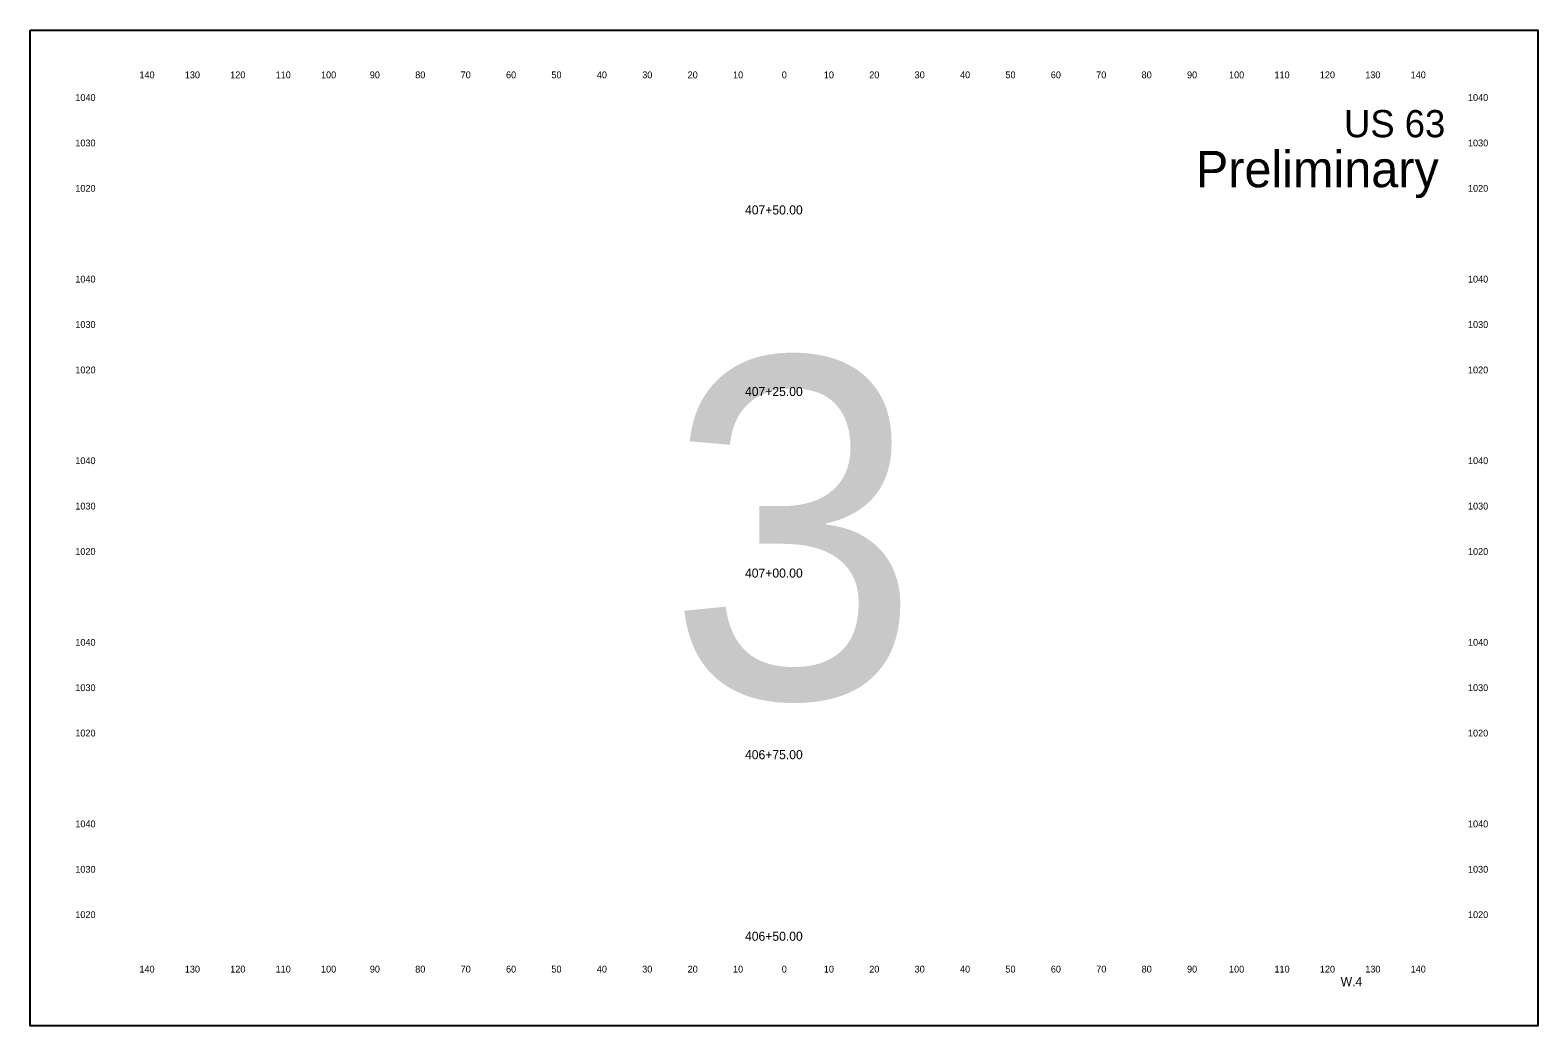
# Model space of a CAD drawing. Extents: x 10123 to 17295, y 9730 to 10181.
# Drawn here: x 10843.2 to 11175.3, y 9730.3 to 9949.6 of the extents above; entities that cross this region are included whole.
import ezdxf

# ---------------------------------------------------------------- set-up
doc = ezdxf.new("R2010")
doc.units = 0
for name, color, linetype in [('dsnTextCpn', 7, 'Continuous'), ('dsnTextCpnTitleSheetLocDesc', 7, 'Continuous'), ('dsnTextCpnTitleSheetPIN', 7, 'Continuous'), ('dsnTextCpnTitleSheetWorkType', 7, 'Continuous')]:
    doc.layers.add(name, color=color, linetype=linetype)

msp = doc.modelspace()

# ---------------------------------------------------------------- linework, layer by layer
at = {"layer": 'dsnTextCpnTitleSheetWorkType'}
msp.add_lwpolyline([(10843.21, 9949.6), (11175.29, 9949.6), (11175.29, 9730.26), (10843.21, 9730.26)], close=True, dxfattribs=at)

# ---------------------------------------------------------------- texts
at = {"layer": 'dsnTextCpn'}
for s, height, p in [('140', 1.5, (10867.27, 9939)), ('130', 1.5, (10877.27, 9939)), ('120', 1.5, (10887.27, 9939)), ('110', 1.5, (10897.27, 9939)), ('100', 1.5, (10907.27, 9939)), ('90', 1.5, (10918.02, 9939)), ('80', 1.5, (10928.02, 9939)), ('70', 1.5, (10938.02, 9939)), ('60', 1.5, (10948.02, 9939)), ('50', 1.5, (10958.02, 9939)), ('40', 1.5, (10968.02, 9939)), ('30', 1.5, (10978.02, 9939)), ('20', 1.5, (10988.02, 9939)), ('10', 1.5, (10998.02, 9939)), ('0', 1.5, (11008.76, 9939)), ('0', 1.5, (11008.76, 9939)), ('10', 1.5, (11018.02, 9939)), ('20', 1.5, (11028.02, 9939)), ('30', 1.5, (11038.02, 9939)), ('40', 1.5, (11048.02, 9939)), ('50', 1.5, (11058.02, 9939)), ('60', 1.5, (11068.02, 9939)), ('70', 1.5, (11078.02, 9939)), ('80', 1.5, (11088.02, 9939)), ('90', 1.5, (11098.02, 9939)), ('100', 1.5, (11107.27, 9939)), ('110', 1.5, (11117.27, 9939)), ('120', 1.5, (11127.27, 9939)), ('130', 1.5, (11137.27, 9939)), ('140', 1.5, (11147.27, 9939)), ('1040', 1.5, (10853.15, 9934)), ('1040', 1.5, (11159.9, 9934)), ('US 63', 6, (11132.6, 9926)), ('1030', 1.5, (10853.15, 9924)), ('1030', 1.5, (11159.9, 9924)), ('1020', 1.5, (10853.15, 9914)), ('1020', 1.5, (11159.9, 9914)), ('407+50.00', 2, (11000.66, 9909)), ('1040', 1.5, (10853.15, 9894)), ('1040', 1.5, (11159.9, 9894)), ('1030', 1.5, (10853.15, 9884)), ('1030', 1.5, (11159.9, 9884)), ('1020', 1.5, (10853.15, 9874)), ('1020', 1.5, (11159.9, 9874)), ('407+25.00', 2, (11000.66, 9869)), ('1040', 1.5, (10853.15, 9854)), ('1040', 1.5, (11159.9, 9854)), ('1030', 1.5, (10853.15, 9844)), ('1030', 1.5, (11159.9, 9844)), ('1020', 1.5, (10853.15, 9834)), ('1020', 1.5, (11159.9, 9834)), ('407+00.00', 2, (11000.66, 9829)), ('1040', 1.5, (10853.15, 9814)), ('1040', 1.5, (11159.9, 9814)), ('1030', 1.5, (10853.15, 9804)), ('1030', 1.5, (11159.9, 9804)), ('1020', 1.5, (10853.15, 9794)), ('1020', 1.5, (11159.9, 9794)), ('406+75.00', 2, (11000.66, 9789)), ('1040', 1.5, (10853.15, 9774)), ('1040', 1.5, (11159.9, 9774)), ('1030', 1.5, (10853.15, 9764)), ('1030', 1.5, (11159.9, 9764)), ('1020', 1.5, (10853.15, 9754)), ('1020', 1.5, (11159.9, 9754)), ('406+50.00', 2, (11000.66, 9749)), ('140', 1.5, (10867.27, 9742)), ('130', 1.5, (10877.27, 9742)), ('120', 1.5, (10887.27, 9742)), ('110', 1.5, (10897.27, 9742)), ('100', 1.5, (10907.27, 9742)), ('90', 1.5, (10918.02, 9742)), ('80', 1.5, (10928.02, 9742)), ('70', 1.5, (10938.02, 9742)), ('60', 1.5, (10948.02, 9742)), ('50', 1.5, (10958.02, 9742)), ('40', 1.5, (10968.02, 9742)), ('30', 1.5, (10978.02, 9742)), ('20', 1.5, (10988.02, 9742)), ('10', 1.5, (10998.02, 9742)), ('0', 1.5, (11008.76, 9742)), ('0', 1.5, (11008.76, 9742)), ('10', 1.5, (11018.02, 9742)), ('20', 1.5, (11028.02, 9742)), ('30', 1.5, (11038.02, 9742)), ('40', 1.5, (11048.02, 9742)), ('50', 1.5, (11058.02, 9742)), ('60', 1.5, (11068.02, 9742)), ('70', 1.5, (11078.02, 9742)), ('80', 1.5, (11088.02, 9742)), ('90', 1.5, (11098.02, 9742)), ('100', 1.5, (11107.27, 9742)), ('110', 1.5, (11117.27, 9742)), ('120', 1.5, (11127.27, 9742)), ('130', 1.5, (11137.27, 9742)), ('140', 1.5, (11147.27, 9742))]:
    msp.add_text(s, height=height, dxfattribs=at).set_placement(p)
at = {"layer": 'dsnTextCpnTitleSheetLocDesc'}
msp.add_text('Preliminary', height=8, dxfattribs=at).set_placement((11099.97, 9915))
at = {"layer": 'dsnTextCpnTitleSheetPIN'}
msp.add_text('W.4', height=2, dxfattribs=at).set_placement((11131.86, 9739))
at = {"layer": 'dsnTextCpnTitleSheetWorkType'}
msp.add_text('3', height=75, dxfattribs=at).set_placement((10983.48, 9802.43))

doc.saveas('drawing.dxf')
